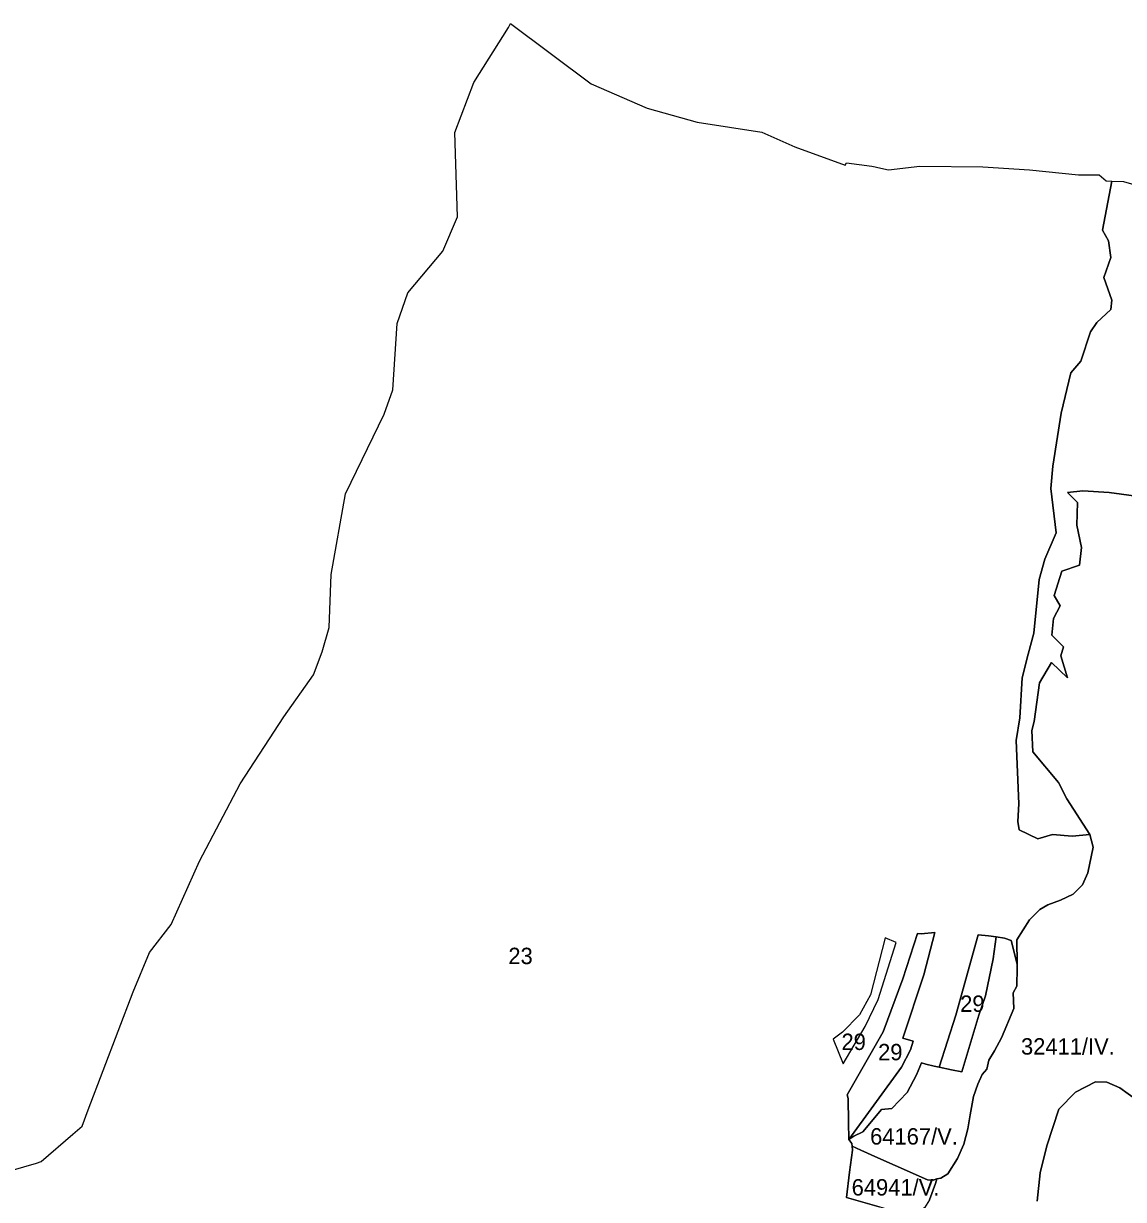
# Model space of a CAD drawing. Extents: x -521621 to -516761, y -1190184 to -1184927.
# Drawn here: x -519686 to -518679, y -1186003 to -1184927 of the extents above; entities that cross this region are included whole.
import ezdxf

# ---------------------------------------------------------------- set-up
doc = ezdxf.new("R2010")
doc.units = 0
doc.layers.add('BPEJ_s', color=7, linetype='Continuous')

msp = doc.modelspace()

# ---------------------------------------------------------------- linework, layer by layer
at = {"layer": 'BPEJ_s'}
for points in [[(-519708.8, -1185979.4), (-519673.8, -1185969.3), (-519669.4, -1185968), (-519640.5, -1185942.8), (-519632.1, -1185935.5), (-519626.4, -1185920.7), (-519585.4, -1185812.8), (-519570.3, -1185776.6), (-519550.5, -1185751), (-519524.6, -1185693.2), (-519487.5, -1185622.5), (-519447.3, -1185561), (-519420.4, -1185522.6), (-519412.2, -1185501.6), (-519405.8, -1185479.2), (-519404.1, -1185430.8), (-519391.1, -1185357), (-519355.6, -1185284.1), (-519347.7, -1185262), (-519343.7, -1185201.1), (-519334, -1185173.2), (-519301.9, -1185135), (-519288.4, -1185103.5), (-519291, -1185026.6), (-519273.4, -1184980.7), (-519241.9, -1184930.3), (-519239.8, -1184926.8), (-519166.2, -1184981.8), (-519115, -1185004.2), (-519069.1, -1185016.9), (-519009.9, -1185026.1), (-518979.8, -1185039.7), (-518933.5, -1185056.4), (-518932.4, -1185054.2), (-518909.2, -1185057.4), (-518906.2, -1185057.9), (-518903.7, -1185058.4), (-518893.9, -1185060.7), (-518865.4, -1185057.4), (-518807.5, -1185058), (-518764.8, -1185060.6), (-518720.1, -1185065.2), (-518701.3, -1185065.2), (-518694.7, -1185070.7), (-518689.5, -1185070.9), (-518698.1, -1185115.7), (-518692.7, -1185125.6), (-518690.4, -1185140.8), (-518697, -1185159.2), (-518689.6, -1185180), (-518690.6, -1185188.4), (-518703.2, -1185200.4), (-518709.1, -1185208.8), (-518718, -1185235.8), (-518727.2, -1185246.4), (-518735.8, -1185283.1), (-518743.5, -1185331.8), (-518745.5, -1185352.1), (-518740.4, -1185392.7), (-518750.9, -1185416.7), (-518756.1, -1185435.3), (-518761, -1185484.4), (-518766.2, -1185503.6), (-518771.7, -1185525.5), (-518773.8, -1185561.9), (-518777.1, -1185582.7), (-518774.6, -1185640.8), (-518775.7, -1185656.9), (-518774.3, -1185664.5), (-518757.4, -1185672.6), (-518744, -1185668.6), (-518725.8, -1185670.2), (-518709.7, -1185668.6), (-518706.7, -1185680.3), (-518711.4, -1185703.8), (-518716.3, -1185714.7), (-518725.1, -1185723.4), (-518736.4, -1185728.8), (-518748, -1185733.2), (-518755.5, -1185737.4), (-518765, -1185746.9), (-518776.6, -1185765.2), (-518776.3, -1185787.5), (-518781.6, -1185765.6), (-518787.8, -1185763.5), (-518795.3, -1185762.2), (-518802.4, -1185761.4), (-518811.9, -1185760.5), (-518832.4, -1185834.1), (-518847.5, -1185881.5), (-518852.1, -1185880.6), (-518859.8, -1185878.7), (-518863.7, -1185877.6), (-518868.2, -1185888.6), (-518876.9, -1185904.7), (-518891, -1185919.4), (-518900.4, -1185920.4), (-518917.4, -1185940.8), (-518925.8, -1185944.7), (-518930.4, -1185947.7), (-518882, -1185881.7), (-518873.7, -1185865.8), (-518871.3, -1185857.9), (-518880.8, -1185855.1), (-518861.7, -1185797), (-518851.6, -1185758.4), (-518864, -1185759.6), (-518867.3, -1185759.3), (-518880.8, -1185800.7), (-518899, -1185849.4), (-518931.9, -1185906.8), (-518930.9, -1185910.3), (-518930.7, -1185932), (-518930.4, -1185947.7), (-518927.4, -1185951.4), (-518927.2, -1185953.9), (-518927, -1185957.5), (-518929.7, -1185977.7), (-518932.5, -1186000.7), (-518902.6, -1186009.3)], [(-518644.7, -1185362.2), (-518692, -1185355.7), (-518716.1, -1185354.2), (-518730, -1185355.7), (-518721.1, -1185364.9), (-518721.7, -1185385.6), (-518717.3, -1185406.1), (-518719.2, -1185422.3), (-518735.2, -1185427.7), (-518742.3, -1185450), (-518736.8, -1185459.5), (-518743, -1185471), (-518744.6, -1185486.5), (-518733.7, -1185497.1), (-518736.2, -1185505.2), (-518730.1, -1185525.3), (-518744.7, -1185511.4), (-518755.9, -1185530), (-518760.7, -1185565.3), (-518762.9, -1185573.7), (-518761.9, -1185593.1), (-518738.3, -1185621.2), (-518730.9, -1185636.2), (-518709.7, -1185668.6), (-518725.8, -1185670.2), (-518744, -1185668.6), (-518757.4, -1185672.6), (-518774.3, -1185664.5), (-518775.7, -1185656.9), (-518774.6, -1185640.8), (-518777.1, -1185582.7), (-518773.8, -1185561.9), (-518771.7, -1185525.5), (-518766.2, -1185503.6), (-518761, -1185484.4), (-518756.1, -1185435.3), (-518750.9, -1185416.7), (-518740.4, -1185392.7), (-518745.5, -1185352.1), (-518743.5, -1185331.8), (-518735.8, -1185283.1), (-518727.2, -1185246.4), (-518718, -1185235.8), (-518709.1, -1185208.8), (-518703.2, -1185200.4), (-518690.6, -1185188.4), (-518689.6, -1185180), (-518697, -1185159.2), (-518690.4, -1185140.8), (-518692.7, -1185125.6), (-518698.1, -1185115.7), (-518689.5, -1185070.9), (-518679, -1185071.3), (-518647.2, -1185080.5)], [(-518856.4, -1186002.9), (-518850.9, -1185988), (-518849.6, -1185983.6), (-518846, -1185983.1), (-518839.6, -1185979.2), (-518830.7, -1185965.2), (-518825.1, -1185951.9), (-518821.3, -1185938.1), (-518819.2, -1185925.2), (-518816.3, -1185908.4), (-518812.3, -1185897.1), (-518808.3, -1185888.3), (-518804, -1185883.3), (-518802.1, -1185875.3), (-518797.1, -1185866.6), (-518790.7, -1185854.9), (-518779.2, -1185827.8), (-518779.8, -1185813.6), (-518776.6, -1185807.5), (-518776.3, -1185790.3), (-518776.3, -1185789.4), (-518776.3, -1185787.5), (-518776.6, -1185765.2), (-518765, -1185746.9), (-518755.5, -1185737.4), (-518748, -1185733.2), (-518736.4, -1185728.8), (-518725.1, -1185723.4), (-518716.3, -1185714.7), (-518711.4, -1185703.8), (-518706.7, -1185680.3), (-518709.7, -1185668.6), (-518730.9, -1185636.2), (-518738.3, -1185621.2), (-518761.9, -1185593.1), (-518762.9, -1185573.7), (-518760.7, -1185565.3), (-518755.9, -1185530), (-518744.7, -1185511.4), (-518730.1, -1185525.3), (-518736.2, -1185505.2), (-518733.7, -1185497.1), (-518744.6, -1185486.5), (-518743, -1185471), (-518736.8, -1185459.5), (-518742.3, -1185450), (-518735.2, -1185427.7), (-518719.2, -1185422.3), (-518717.3, -1185406.1), (-518721.7, -1185385.6), (-518721.1, -1185364.9), (-518730, -1185355.7), (-518716.1, -1185354.2), (-518692, -1185355.7), (-518644.7, -1185362.2)], [(-518758, -1186004.2), (-518755.3, -1185978.2), (-518749.1, -1185953.6), (-518738.2, -1185920.1), (-518722.8, -1185904.4), (-518704.5, -1185895), (-518694.1, -1185895.3), (-518682.3, -1185900.6), (-518666.9, -1185911.6), (-518653.6, -1185925.2), (-518656.2, -1185952.1), (-518658.6, -1185978.5), (-518663.3, -1185999.2), (-518663.9, -1186020.8)], [(-518666.9, -1185911.6), (-518682.3, -1185900.6), (-518694.1, -1185895.3), (-518704.5, -1185895), (-518722.8, -1185904.4), (-518738.2, -1185920.1), (-518749.1, -1185953.6), (-518755.3, -1185978.2), (-518758, -1186004.2)]]:
    msp.add_lwpolyline(points, dxfattribs=at)
for points in [[(-518930.4, -1185947.7), (-518930.7, -1185932), (-518930.9, -1185910.3), (-518931.9, -1185906.8), (-518899, -1185849.4), (-518880.8, -1185800.7), (-518867.3, -1185759.3), (-518864, -1185759.6), (-518851.6, -1185758.4), (-518861.7, -1185797), (-518880.8, -1185855.1), (-518871.3, -1185857.9), (-518873.7, -1185865.8), (-518882, -1185881.7)], [(-518886.9, -1185767.6), (-518896.9, -1185763.4), (-518910.6, -1185815.4), (-518920.5, -1185833.6), (-518936, -1185849.5), (-518944.5, -1185856), (-518935.4, -1185878.4), (-518915.4, -1185844.4), (-518903.5, -1185819.7)], [(-518886.9, -1185767.6), (-518896.9, -1185763.4), (-518910.6, -1185815.4), (-518920.5, -1185833.6), (-518936, -1185849.5), (-518944.5, -1185856), (-518935.4, -1185878.4), (-518915.4, -1185844.4), (-518903.5, -1185819.7)], [(-518930.4, -1185947.7), (-518925.8, -1185944.7), (-518917.4, -1185940.8), (-518900.4, -1185920.4), (-518891, -1185919.4), (-518876.9, -1185904.7), (-518868.2, -1185888.6), (-518863.7, -1185877.6), (-518859.8, -1185878.7), (-518852.1, -1185880.6), (-518847.5, -1185881.5), (-518836.4, -1185883.9), (-518827, -1185885.9), (-518811.2, -1185834), (-518805.1, -1185816.4), (-518798.3, -1185782.5), (-518795.3, -1185762.2), (-518787.8, -1185763.5), (-518781.6, -1185765.6), (-518776.3, -1185787.5), (-518776.3, -1185789.4), (-518776.3, -1185790.3), (-518776.6, -1185807.5), (-518779.8, -1185813.6), (-518779.2, -1185827.8), (-518790.7, -1185854.9), (-518797.1, -1185866.6), (-518802.1, -1185875.3), (-518804, -1185883.3), (-518808.3, -1185888.3), (-518812.3, -1185897.1), (-518816.3, -1185908.4), (-518819.2, -1185925.2), (-518821.3, -1185938.1), (-518825.1, -1185951.9), (-518830.7, -1185965.2), (-518839.6, -1185979.2), (-518846, -1185983.1), (-518849.6, -1185983.6), (-518853.2, -1185985), (-518858.3, -1185984.6), (-518887.8, -1185971.7), (-518903.6, -1185964.5), (-518919.2, -1185957.5), (-518927.2, -1185953.9), (-518927.4, -1185951.4)], [(-518847.5, -1185881.5), (-518832.4, -1185834.1), (-518811.9, -1185760.5), (-518802.4, -1185761.4), (-518795.3, -1185762.2), (-518798.3, -1185782.5), (-518805.1, -1185816.4), (-518811.2, -1185834), (-518827, -1185885.9), (-518836.4, -1185883.9)], [(-518927.2, -1185953.9), (-518919.2, -1185957.5), (-518903.6, -1185964.5), (-518887.8, -1185971.7), (-518858.3, -1185984.6), (-518853.2, -1185985), (-518849.6, -1185983.6), (-518850.9, -1185988), (-518856.4, -1186002.9), (-518861, -1186010.4), (-518869.1, -1186015.1), (-518894.5, -1186011.7), (-518902.6, -1186009.3), (-518932.5, -1186000.7), (-518929.7, -1185977.7), (-518927, -1185957.5)]]:
    msp.add_lwpolyline(points, close=True, dxfattribs=at)

# ---------------------------------------------------------------- texts
for s, p in [('23', (-519241.9, -1185787.3)), ('29', (-518828.4, -1185831)), ('29', (-518937, -1185865.9)), ('32411/IV.', (-518772.7, -1185870.1)), ('29', (-518903.5, -1185875.3)), ('64167/V.', (-518910.8, -1185952.4)), ('64941/V.', (-518927.7, -1185999))]:
    msp.add_text(s, height=15, dxfattribs=at).set_placement(p)

doc.saveas('drawing.dxf')
